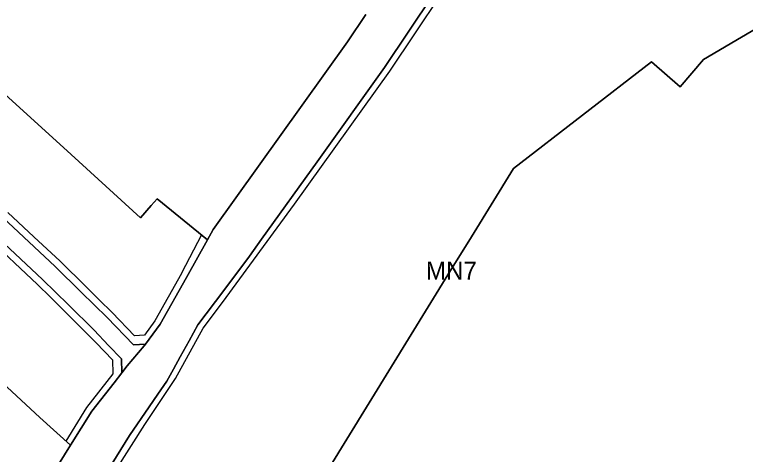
# Model space of a CAD drawing. Extents: x 7439486 to 7443435, y 5551288 to 5554556.
# Drawn here: x 7440958.3 to 7441363, y 5552903.8 to 5553147.6 of the extents above; entities that cross this region are included whole.
import ezdxf

# ---------------------------------------------------------------- set-up
doc = ezdxf.new("R2010")
doc.units = 0
for name, color, linetype in [('linie_rozgraniczajace', 7, 'Continuous'), ('linie_zabudowy_nieprzekraczalne', 7, 'Continuous'), ('oznaczenia_przeznaczen', 7, 'Continuous')]:
    doc.layers.add(name, color=color, linetype=linetype)

msp = doc.modelspace()

# ---------------------------------------------------------------- linework, layer by layer
at = {"layer": 'linie_rozgraniczajace'}
for points in [[(7441004.21, 5552885.58), (7441021.96, 5552914.19), (7441032.79, 5552930.21), (7441037.68, 5552937.27), (7441042.56, 5552944.33), (7441046.31, 5552951.11), (7441050.05, 5552957.88), (7441054.89, 5552966.78), (7441059.73, 5552975.68), (7441074.06, 5552994.68), (7441088.38, 5553013.69), (7441095.08, 5553023.14), (7441125.78, 5553065.97), (7441163.18, 5553118.25), (7441190.17, 5553158.74), (7441205.81, 5553182.2), (7441214.23, 5553188.01), (7441248.05, 5553196.36), (7441287.05, 5553207.02), (7441331.46, 5553224.04), (7441368.14, 5553241.69)], [(7441190.17, 5553158.74), (7441163.18, 5553118.25), (7441125.78, 5553065.97), (7441095.08, 5553023.14), (7441088.38, 5553013.69), (7441074.06, 5552994.68), (7441059.73, 5552975.68), (7441054.89, 5552966.78), (7441050.05, 5552957.88), (7441046.31, 5552951.11), (7441042.56, 5552944.33), (7441037.68, 5552937.27), (7441032.79, 5552930.21), (7441021.96, 5552914.19), (7441004.21, 5552885.58)], [(7441152.78, 5553147.71), (7441142.61, 5553132.46), (7441068.23, 5553028.48), (7441065.02, 5553022.72), (7441037.26, 5553045.48), (7441033.99, 5553041.72), (7441027.91, 5553035.03), (7441008.73, 5553052.51), (7440989.56, 5553069.98), (7440946.6, 5553109.13)], [(7440965.44, 5552870.5), (7440989.22, 5552908.83), (7441000.98, 5552927.78), (7441013.38, 5552943.45), (7441017.69, 5552949.06), (7441020.57, 5552952.81), (7441030.09, 5552963.97), (7441030.74, 5552964.84), (7441038.95, 5552975.9), (7441053.43, 5553001.9), (7441065.02, 5553022.72), (7441068.23, 5553028.48), (7441142.61, 5553132.46), (7441152.78, 5553147.71)], [(7441030.31, 5552730.01), (7441199.76, 5553005.69), (7441211.32, 5553024.5), (7441234.59, 5553062.35), (7441311, 5553121.41), (7441326.85, 5553107.57), (7441339.88, 5553122.65), (7441381.86, 5553147.53)], [(7441381.86, 5553147.53), (7441339.88, 5553122.65), (7441326.85, 5553107.57), (7441311, 5553121.41), (7441234.59, 5553062.35), (7441211.32, 5553024.5), (7441199.76, 5553005.69), (7441030.31, 5552730.01)], [(7440946.6, 5553109.13), (7440989.56, 5553069.98), (7441008.73, 5553052.51), (7441027.91, 5553035.03), (7441033.99, 5553041.72), (7441037.26, 5553045.48), (7441065.02, 5553022.72), (7441053.43, 5553001.9), (7441038.95, 5552975.9), (7441030.74, 5552964.84), (7441024.07, 5552964.57), (7441009.44, 5552979.6), (7440995.05, 5552993.8), (7440980.66, 5553008.01), (7440951.81, 5553035.08)], [(7440916.19, 5553054.79), (7440973.72, 5553000.81), (7440988.02, 5552986.69), (7441002.32, 5552972.58), (7441010.34, 5552964.12), (7441017.38, 5552956.68), (7441017.69, 5552949.06), (7441013.38, 5552943.45), (7441000.98, 5552927.78), (7440989.22, 5552908.83), (7440972.23, 5552924.19), (7440941.08, 5552953.1)], [(7440951.81, 5553035.08), (7440980.66, 5553008.01), (7440995.05, 5552993.8), (7441009.44, 5552979.6), (7441024.07, 5552964.57), (7441030.74, 5552964.84), (7441030.09, 5552963.97), (7441020.57, 5552952.81), (7441017.69, 5552949.06), (7441017.38, 5552956.68), (7441010.34, 5552964.12), (7441002.32, 5552972.58), (7440988.02, 5552986.69), (7440973.72, 5553000.81), (7440916.19, 5553054.79)], [(7440941.08, 5552953.1), (7440972.23, 5552924.19), (7440989.22, 5552908.83), (7440965.44, 5552870.5)]]:
    msp.add_lwpolyline(points, dxfattribs=at)
at = {"layer": 'linie_zabudowy_nieprzekraczalne'}
for points in [[(7440979.56, 5552840.3), (7441030.3, 5552920.28), (7441047.45, 5552945.95), (7441062.68, 5552973.78), (7441073.35, 5552987.94), (7441113.27, 5553042.52), (7441166.06, 5553116.27), (7441208.35, 5553179.7), (7441216.85, 5553185.57), (7441258.57, 5553196.13), (7441287.98, 5553204.16), (7441332.65, 5553221.29), (7441383.71, 5553245.85)], [(7441061.74, 5553025.45), (7441050.79, 5553004.35), (7441050.63, 5553004.08), (7441036, 5552977.79), (7441030.14, 5552969.82), (7441024.75, 5552969.6), (7441012.28, 5552982.41), (7441005.07, 5552989.54), (7440997.86, 5552996.65), (7440983.43, 5553010.9), (7440968.98, 5553024.45), (7440954.55, 5553037.99)], [(7440942.21, 5553024.89), (7440970.95, 5552997.93), (7440978.08, 5552990.89), (7440985.21, 5552983.85), (7440992.34, 5552976.81), (7440999.46, 5552969.78), (7441003.44, 5552965.58), (7441012.4, 5552956.13), (7441012.72, 5552948.39), (7440998.11, 5552929.79), (7440986.57, 5552911.19)]]:
    msp.add_lwpolyline(points, dxfattribs=at)

# ---------------------------------------------------------------- texts
at = {"layer": 'oznaczenia_przeznaczen'}
msp.add_text('MN7', height=10, dxfattribs=at).set_placement((7441186.06, 5553000.69))

doc.saveas('drawing.dxf')
